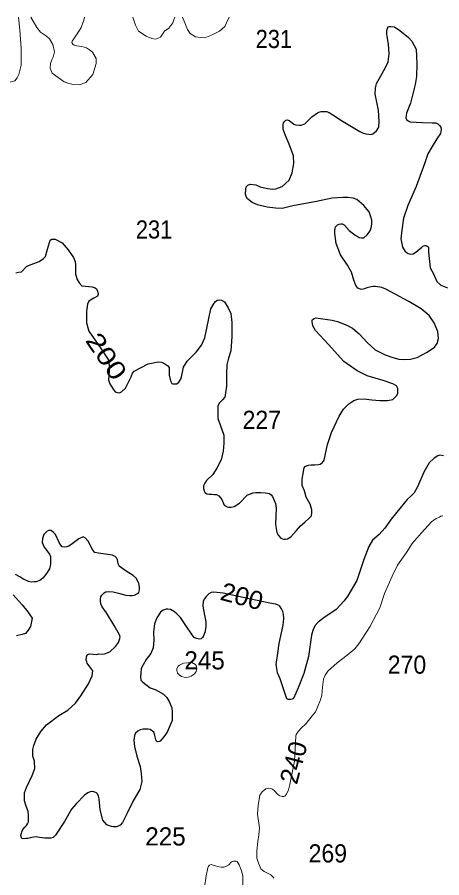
# Model space of a CAD drawing. Extents: x 445.4 to 500, y 8728.7 to 8784.
# Drawn here: x 489.69 to 493.44, y 8776.42 to 8784.01 of the extents above; entities that cross this region are included whole.
import ezdxf
from ezdxf.enums import TextEntityAlignment as Align

# ---------------------------------------------------------------- set-up
doc = ezdxf.new("R2010")
doc.units = 0
doc.header["$LTSCALE"] = 0.064
doc.layers.add('1', color=7, linetype='Continuous', lineweight=25)
doc.layers.add('2', color=7, linetype='Continuous', lineweight=13)
doc.layers.add('21', color=7, linetype='Continuous')
doc.layers.add('61', color=7, linetype='Continuous')

msp = doc.modelspace()

# ---------------------------------------------------------------- linework, layer by layer
at = {"layer": '1'}
for points in [[(492.1344, 8782.7141), (492.1312, 8782.7843), (492.095, 8782.8864), (492.0663, 8782.9468), (492.0418, 8783.0159), (492.0407, 8783.0414), (492.0418, 8783.0606), (492.0439, 8783.0744), (492.0524, 8783.0872), (492.0642, 8783.0967), (492.0759, 8783.0999), (492.094, 8783.0936), (492.1174, 8783.0765), (492.1344, 8783.0627), (492.1525, 8783.0553), (492.1813, 8783.0531), (492.2004, 8783.0531), (492.2313, 8783.0659), (492.2952, 8783.1276), (492.3431, 8783.1627), (492.3559, 8783.1691), (492.3771, 8783.1733), (492.407, 8783.1733), (492.4229, 8783.1733), (492.4463, 8783.1648), (492.4794, 8783.1446), (492.5549, 8783.0936), (492.6281, 8783.0495), (492.7165, 8782.9985), (492.741, 8782.9868), (492.7708, 8782.9783), (492.7963, 8782.973), (492.8155, 8782.9709), (492.8336, 8782.9772), (492.8655, 8783.0049), (492.8847, 8783.0357), (492.889, 8783.0846), (492.8808, 8783.1864), (492.852, 8783.3257), (492.8553, 8783.3806), (492.8638, 8783.4199), (492.899, 8783.4826), (492.9426, 8783.5624), (492.9684, 8783.6132), (492.9769, 8783.6833), (492.9716, 8783.7684), (492.9577, 8783.8354), (492.9556, 8783.8599), (492.9566, 8783.8833), (492.963, 8783.9077), (492.9705, 8783.9194), (492.9769, 8783.9237), (492.9918, 8783.9247), (493.0237, 8783.9194), (493.0706, 8783.8875), (493.1472, 8783.828), (493.177, 8783.7939), (493.2143, 8783.7248), (493.2217, 8783.593), (493.2176, 8783.4815), (493.2059, 8783.4114), (493.1654, 8783.2487), (493.1291, 8783.1595), (493.1259, 8783.1404), (493.1237, 8783.118), (493.1291, 8783.1042), (493.145, 8783.0904), (493.1631, 8783.083), (493.2685, 8783.0776), (493.3548, 8783.0755), (493.3878, 8783.0734), (493.4048, 8783.0659), (493.4208, 8783.0511), (493.4325, 8783.0351), (493.4367, 8783.016), (493.4293, 8782.9798), (493.3973, 8782.932), (493.3554, 8782.8664), (493.3182, 8782.8013), (493.2902, 8782.7199), (493.2157, 8782.5133), (493.1412, 8782.3459), (493.1038, 8782.2328), (493.0871, 8782.1267), (493.0796, 8782.0523), (493.0945, 8781.9778), (493.1187, 8781.9406), (493.1448, 8781.922), (493.1672, 8781.9146), (493.1877, 8781.9174), (493.2125, 8781.9327), (493.2638, 8781.9789), (493.2749, 8781.9849), (493.2903, 8781.9908), (493.3014, 8781.9925), (493.31, 8781.99), (493.3228, 8781.9789), (493.3237, 8781.9327), (493.3391, 8781.7944), (493.3666, 8781.7425), (493.3982, 8781.6733)], [(492.5767, 8780.9688), (492.4404, 8781.1198), (492.3251, 8781.2429), (492.3038, 8781.2823), (492.2985, 8781.3004), (492.2974, 8781.3184), (492.2963, 8781.3323), (492.2995, 8781.3408), (492.3134, 8781.3482), (492.3283, 8781.3535), (492.3485, 8781.3525), (492.4731, 8781.3323), (492.5199, 8781.3227), (492.6029, 8781.2908), (492.6519, 8781.2642), (492.7113, 8781.2116), (492.7815, 8781.1361), (492.8539, 8781.0734), (492.9423, 8781.0266), (493.0083, 8781.0053), (493.0605, 8780.9894), (493.1158, 8780.9873), (493.1644, 8780.9901), (493.225, 8781.005), (493.3123, 8781.0517), (493.3752, 8781.0943), (493.4011, 8781.128), (493.4106, 8781.1705), (493.4053, 8781.2333), (493.3723, 8781.3098), (493.3297, 8781.3736), (493.2584, 8781.4332), (493.1514, 8781.4969), (492.9459, 8781.6075), (492.9123, 8781.6203), (492.8569, 8781.6309), (492.8356, 8781.6309), (492.8175, 8781.6288), (492.7781, 8781.6181), (492.7579, 8781.6086), (492.7355, 8781.6054), (492.7228, 8781.6064), (492.6993, 8781.6149), (492.6823, 8781.6394), (492.6642, 8781.6862), (492.6429, 8781.7564), (492.6085, 8781.8198), (492.5478, 8781.9102), (492.5095, 8782.0102), (492.4978, 8782.098), (492.4967, 8782.1257), (492.4989, 8782.1459), (492.5031, 8782.1555), (492.5116, 8782.1661), (492.5212, 8782.1735), (492.535, 8782.181), (492.5489, 8782.1831), (492.5606, 8782.1831), (492.5798, 8782.1746), (492.6234, 8782.1236), (492.6756, 8782.0832), (492.6947, 8782.0736), (492.7128, 8782.064), (492.7331, 8782.0598), (492.7533, 8782.0598), (492.781, 8782.0874), (492.8076, 8782.1204), (492.8172, 8782.148), (492.8236, 8782.1789), (492.8225, 8782.2161), (492.814, 8782.2448), (492.8012, 8782.2895), (492.7533, 8782.3448), (492.6914, 8782.3965), (492.6574, 8782.4082), (492.6159, 8782.4146), (492.568, 8782.4146), (492.4732, 8782.4093), (492.3337, 8782.3795), (492.1261, 8782.3412), (492.0316, 8782.3196), (491.972, 8782.3207), (491.8985, 8782.3313), (491.8155, 8782.3505), (491.7665, 8782.3707), (491.7271, 8782.4047), (491.7133, 8782.4249), (491.708, 8782.4462), (491.7101, 8782.4898), (491.7144, 8782.5089), (491.7293, 8782.5249), (491.7506, 8782.5323), (491.7985, 8782.5259), (491.8389, 8782.51), (491.9017, 8782.494), (491.9481, 8782.4903), (491.9768, 8782.4924), (492.0311, 8782.5126), (492.095, 8782.569), (492.1216, 8782.6328), (492.1344, 8782.7141)], [(489.6822, 8781.7506), (489.7035, 8781.7556), (489.7298, 8781.7605), (489.7758, 8781.8064), (489.7922, 8781.8146), (489.8857, 8781.8506), (489.9251, 8781.8769), (489.9431, 8781.8949), (489.9612, 8781.9588), (489.977, 8782.018), (489.9852, 8782.0393), (490, 8782.0492), (490.0279, 8782.0492), (490.0886, 8782.0148), (490.1428, 8781.9541), (490.1904, 8781.8869), (490.2051, 8781.8508), (490.2084, 8781.8197), (490.2084, 8781.7394), (490.2232, 8781.6935), (490.2398, 8781.6629), (490.2645, 8781.6367), (490.2956, 8781.6334), (490.3547, 8781.6268), (490.381, 8781.6186), (490.3925, 8781.6088), (490.4007, 8781.5891), (490.4072, 8781.5629), (490.4007, 8781.5449), (490.3695, 8781.5285), (490.3252, 8781.5023), (490.312, 8781.4744), (490.3055, 8781.4121), (490.3055, 8781.3105), (490.3252, 8781.2372), (490.4352, 8781.0799), (490.4959, 8780.9881), (490.509, 8780.9192), (490.4992, 8780.8061), (490.5095, 8780.7723), (490.539, 8780.7264), (490.5571, 8780.7018), (490.5751, 8780.6952), (490.5964, 8780.6936), (490.6129, 8780.7002), (490.649, 8780.733), (490.6982, 8780.8346), (490.7113, 8780.8657), (490.7261, 8780.8838), (490.8492, 8780.9477), (490.9361, 8780.9657), (490.9673, 8780.9624), (490.9883, 8780.9537), (491.0213, 8780.9303), (491.0341, 8780.9175), (491.0352, 8780.8473), (491.0448, 8780.7984), (491.0565, 8780.7761), (491.066, 8780.7718), (491.082, 8780.7708), (491.1022, 8780.7729), (491.1203, 8780.7857), (491.1406, 8780.8197), (491.1597, 8780.9197), (491.1938, 8780.9728), (491.2736, 8781.0526), (491.3188, 8781.1118), (491.3497, 8781.1778), (491.3859, 8781.3469), (491.4031, 8781.4338), (491.4307, 8781.4837), (491.4414, 8781.4965), (491.4595, 8781.5093), (491.4755, 8781.5125), (491.4978, 8781.5114), (491.5223, 8781.4954), (491.5564, 8781.4412), (491.5787, 8781.3934), (491.5872, 8781.3125), (491.5885, 8781.1884), (491.5789, 8781.064), (491.5576, 8780.9973), (491.5448, 8780.9388), (491.5405, 8780.8602)], [(493.3982, 8781.6733), (493.4333, 8781.6417), (493.4905, 8781.6195)], [(491.5405, 8780.8602), (491.5405, 8780.7506), (491.5309, 8780.6924), (491.5245, 8780.6552), (491.5065, 8780.6318), (491.4745, 8780.602), (491.4649, 8780.5744), (491.4628, 8780.5138), (491.4649, 8780.4659), (491.4852, 8780.4111), (491.516, 8780.3185), (491.516, 8780.2473), (491.5097, 8780.1771), (491.4926, 8780.1018), (491.4564, 8780.0273), (491.4202, 8779.972), (491.3627, 8779.9199), (491.3478, 8779.8965), (491.3382, 8779.871), (491.3382, 8779.8498), (491.3425, 8779.8296), (491.3478, 8779.8147), (491.3672, 8779.8013), (491.3863, 8779.8002), (491.4097, 8779.7992), (491.4353, 8779.7971), (491.4534, 8779.7949), (491.4715, 8779.7854), (491.4981, 8779.7524), (491.5194, 8779.7013), (491.545, 8779.6875), (491.5599, 8779.6854), (491.5822, 8779.6843), (491.6088, 8779.6897), (491.6557, 8779.7194), (491.7227, 8779.7896), (491.7717, 8779.8109), (491.7994, 8779.8141), (491.8409, 8779.8151), (491.8835, 8779.8109), (491.9186, 8779.8056), (491.9346, 8779.7928), (491.9474, 8779.779), (491.9719, 8779.7173), (491.9787, 8779.6753), (491.9734, 8779.5328), (491.9851, 8779.4615), (491.9989, 8779.435), (492.0202, 8779.4094), (492.0351, 8779.4041), (492.0479, 8779.4031), (492.0607, 8779.4031), (492.0777, 8779.4062), (492.1086, 8779.4222), (492.1576, 8779.4786), (492.1938, 8779.5211), (492.231, 8779.5509), (492.2715, 8779.586), (492.2896, 8779.6083), (492.2949, 8779.6338), (492.2938, 8779.6615), (492.2779, 8779.7114), (492.245, 8779.7717), (492.2291, 8779.8292), (492.2078, 8779.8759), (492.2078, 8779.9302), (492.2269, 8780.0312), (492.2345, 8780.0426), (492.2462, 8780.0501), (492.2654, 8780.0543), (492.2867, 8780.0575), (492.3197, 8780.0575), (492.3516, 8780.0618), (492.3665, 8780.065), (492.3804, 8780.0713), (492.3889, 8780.0788), (492.4038, 8780.0979), (492.4315, 8780.2372), (492.4666, 8780.3425), (492.5341, 8780.4879), (492.5735, 8780.5485), (492.6203, 8780.5942), (492.664, 8780.625), (492.6991, 8780.6357), (492.7555, 8780.6389), (492.8231, 8780.63), (492.8944, 8780.6247), (492.9626, 8780.6236), (493.0094, 8780.6353), (493.0264, 8780.6513), (493.0445, 8780.6683), (493.0531, 8780.6885), (493.0531, 8780.7066), (493.0531, 8780.7299), (493.0477, 8780.7438), (493.0403, 8780.7555), (493.0083, 8780.7725), (492.9242, 8780.8012), (492.7816, 8780.8416), (492.6938, 8780.888), (492.5767, 8780.9688)], [(493.4559, 8780.1383), (493.4248, 8780.142), (493.4047, 8780.1365), (493.3736, 8780.1173), (493.3306, 8780.0753), (493.2828, 8779.9916), (493.2279, 8779.8628), (493.197, 8779.8113), (493.1673, 8779.7799), (493.1341, 8779.752), (493.0428, 8779.6413), (492.9939, 8779.5784), (492.938, 8779.4982), (492.8891, 8779.4424), (492.828, 8779.3918), (492.7983, 8779.3359), (492.7542, 8779.2214), (492.6896, 8779.0365), (492.6101, 8778.903), (492.5791, 8778.8567), (492.5075, 8778.7812), (492.3986, 8778.7073), (492.3483, 8778.6689), (492.32, 8778.6366), (492.3026, 8778.5963), (492.2918, 8778.5547), (492.2649, 8778.368), (492.2245, 8778.2181), (492.1734, 8778.0918), (492.1317, 8777.9978), (492.121, 8777.991), (492.1089, 8777.9884), (492.0994, 8777.9884), (492.086, 8777.9884), (492.0739, 8777.9951), (492.0698, 8778.0031), (492.0134, 8778.171), (491.9905, 8778.2221), (491.9878, 8778.2422), (491.9851, 8778.2637), (491.9797, 8778.2973), (491.9945, 8778.3954), (492.0068, 8778.4823), (492.0417, 8778.6435), (492.0458, 8778.7013), (492.0431, 8778.7403), (492.0377, 8778.7631), (492.0269, 8778.7873), (492.0108, 8778.8115), (491.992, 8778.8222), (491.9718, 8778.8276), (491.9217, 8778.8365), (491.7563, 8778.8714), (491.512, 8778.9252), (491.4299, 8778.936), (491.4057, 8778.9319), (491.3842, 8778.9185), (491.36, 8778.897), (491.3465, 8778.8769), (491.3358, 8778.8554), (491.3304, 8778.811), (491.3452, 8778.7304), (491.3573, 8778.6717), (491.3573, 8778.6287), (491.3506, 8778.579), (491.3385, 8778.5481), (491.3277, 8778.5333), (491.3156, 8778.5226), (491.3008, 8778.5199), (491.2766, 8778.5266), (491.2565, 8778.5333), (491.2363, 8778.5575), (491.1811, 8778.6408), (491.1341, 8778.712), (491.1031, 8778.7442), (491.0803, 8778.7617), (491.0474, 8778.782), (491.0219, 8778.7847), (491.0084, 8778.7847), (490.9802, 8778.7753), (490.9587, 8778.7579), (490.9264, 8778.7095), (490.9049, 8778.6558), (490.8968, 8778.5859), (490.8981, 8778.5093), (490.8926, 8778.444), (490.8725, 8778.3929), (490.8321, 8778.3406)], [(489.849, 8777.378), (489.8449, 8777.4438), (489.8315, 8777.4895), (489.8301, 8777.5137), (489.8301, 8777.5459), (489.8395, 8777.5835), (489.8611, 8777.6373), (489.9001, 8777.7071), (489.9515, 8777.7657), (490.0604, 8777.8463), (490.1411, 8777.8947), (490.207, 8777.9565), (490.2544, 8778.0191), (490.323, 8778.1266), (490.3533, 8778.1963), (490.36, 8778.2396), (490.3333, 8778.2762), (490.3099, 8778.3095), (490.3066, 8778.3212), (490.3016, 8778.3379), (490.3049, 8778.3628), (490.3133, 8778.3845), (490.33, 8778.3895), (490.3633, 8778.3878), (490.3917, 8778.3862), (490.4117, 8778.3895), (490.445, 8778.3878), (490.4634, 8778.3912), (490.5117, 8778.4095), (490.562, 8778.4553), (490.587, 8778.4903), (490.597, 8778.517), (490.6004, 8778.5386), (490.597, 8778.5586), (490.5503, 8778.6419), (490.482, 8778.7535), (490.442, 8778.8064), (490.432, 8778.8313), (490.4286, 8778.858), (490.427, 8778.878), (490.4303, 8778.893), (490.4386, 8778.908), (490.4503, 8778.9196), (490.462, 8778.9296), (490.4753, 8778.9363), (490.5003, 8778.9396), (490.5404, 8778.9379), (490.5871, 8778.9246), (490.6521, 8778.908), (490.6838, 8778.9063), (490.7071, 8778.9063), (490.7271, 8778.908), (490.7538, 8778.923), (490.7655, 8778.933), (490.7722, 8778.9563), (490.7722, 8778.9796), (490.7672, 8779.0112), (490.7455, 8779.0562), (490.7155, 8779.0829), (490.6538, 8779.1212), (490.6137, 8779.1495), (490.5937, 8779.1645), (490.5937, 8779.1645), (490.5837, 8779.1861), (490.5821, 8779.2061), (490.5771, 8779.2195), (490.5687, 8779.2361), (490.557, 8779.2494), (490.5333, 8779.2623), (490.4716, 8779.269), (490.4116, 8779.279), (490.3782, 8779.2856), (490.3599, 8779.3039), (490.3182, 8779.3856), (490.2965, 8779.4122), (490.2765, 8779.4222), (490.2365, 8779.4056), (490.1781, 8779.3622), (490.1481, 8779.3389), (490.1297, 8779.3339), (490.1081, 8779.3323), (490.0897, 8779.3356), (490.078, 8779.3489), (490.0647, 8779.3722), (490.0297, 8779.4422), (490.0147, 8779.4622), (489.9913, 8779.4788), (489.973, 8779.4788), (489.9563, 8779.4738), (489.928, 8779.4439), (489.9163, 8779.4072), (489.9146, 8779.3722), (489.9296, 8779.3306), (489.978, 8779.2706), (489.988, 8779.2506), (489.9855, 8779.1814), (489.9789, 8779.1398), (489.9522, 8779.0981), (489.9188, 8779.0581), (489.8922, 8779.0365), (489.8605, 8779.0248)], [(489.8605, 8779.0248), (489.8421, 8779.0248), (489.8188, 8779.0232), (489.7921, 8779.0282), (489.7437, 8779.0515), (489.7154, 8779.0698), (489.6787, 8779.0898)], [(489.6587, 8778.9116), (489.7354, 8778.8233), (489.7855, 8778.7605), (489.8055, 8778.7339), (489.8238, 8778.7039), (489.8105, 8778.6306), (489.7888, 8778.6006), (489.7671, 8778.569), (489.7354, 8778.5606), (489.6854, 8778.5506)], [(490.8321, 8778.3406), (490.8039, 8778.2949), (490.7877, 8778.26), (490.785, 8778.221), (490.7823, 8778.1888), (490.785, 8778.1592), (490.8012, 8778.1404), (490.8657, 8778.092), (490.9104, 8778.0749), (490.9844, 8778.0346), (491.0127, 8778.0064), (491.0355, 8777.9701), (491.0584, 8777.915), (491.0611, 8777.876), (491.0597, 8777.8022), (491.018, 8777.6987), (490.9881, 8777.6575), (490.9558, 8777.6212), (490.949, 8777.6185), (490.949, 8777.6185), (490.9289, 8777.6145), (490.9222, 8777.6212), (490.9181, 8777.6319), (490.9141, 8777.6481), (490.9087, 8777.6696), (490.8979, 8777.6991), (490.867, 8777.7246), (490.8468, 8777.7273), (490.8038, 8777.726), (490.7769, 8777.7193), (490.7567, 8777.7099), (490.7379, 8777.691), (490.7271, 8777.6709), (490.7218, 8777.6279), (490.7298, 8777.5728), (490.7487, 8777.4869), (490.7769, 8777.3982), (490.7877, 8777.3355), (490.7944, 8777.2657), (490.7742, 8777.1945), (490.7177, 8777.095), (490.664, 8776.9862), (490.6219, 8776.902), (490.6031, 8776.8805), (490.5909, 8776.8725), (490.5775, 8776.8671), (490.5694, 8776.8658), (490.5439, 8776.8644), (490.525, 8776.8684), (490.5076, 8776.8738), (490.4834, 8776.8832), (490.4659, 8776.9034), (490.4484, 8776.9235), (490.4255, 8777.0135), (490.4173, 8777.111), (490.4092, 8777.1352), (490.4012, 8777.1554), (490.3931, 8777.1634), (490.3796, 8777.1715), (490.3595, 8777.1755), (490.3379, 8777.1742), (490.3164, 8777.1634), (490.2882, 8777.1446), (490.2129, 8777.0681), (490.1733, 8777.0204), (490.1115, 8776.9129), (490.0321, 8776.792), (490.0106, 8776.7705), (489.9891, 8776.7638), (489.9824, 8776.7638), (489.9649, 8776.7638), (489.938, 8776.7638), (489.9151, 8776.7678), (489.8909, 8776.7705), (489.86, 8776.7772), (489.8385, 8776.7746), (489.821, 8776.7705), (489.786, 8776.7625), (489.7699, 8776.7611), (489.7511, 8776.7598), (489.7349, 8776.7611), (489.7295, 8776.7678), (489.7295, 8776.7678), (489.7255, 8776.7893), (489.7295, 8776.8081), (489.7349, 8776.8216), (489.743, 8776.8417), (489.7605, 8776.8619), (489.7739, 8776.878), (489.7833, 8776.8901), (489.7914, 8776.9102), (489.7927, 8776.9358), (489.7927, 8776.9667), (489.7901, 8776.9989), (489.7685, 8777.0567), (489.7575, 8777.0936), (489.7575, 8777.1232), (489.7575, 8777.1662), (489.775, 8777.2118), (489.8247, 8777.3166), (489.849, 8777.378)]]:
    msp.add_lwpolyline(points, dxfattribs=at)
at = {"layer": '2'}
for points in [[(489.2057, 8784.0049), (489.2054, 8783.9521), (489.2246, 8783.9234), (489.2318, 8783.8971), (489.2342, 8783.8445), (489.2509, 8783.7609), (489.337, 8783.6486), (489.5213, 8783.467), (489.5452, 8783.4455), (489.5787, 8783.4408), (489.6122, 8783.4288), (489.6481, 8783.4384), (489.672, 8783.4455), (489.6935, 8783.4718), (489.7079, 8783.5005), (489.727, 8783.5817), (489.727, 8783.7322), (489.7175, 8783.8899), (489.7029, 8784.005)], [(489.814, 8784.0051), (489.8658, 8783.9138), (489.8993, 8783.8732), (489.9519, 8783.8374), (489.9783, 8783.8135), (490.007, 8783.7657), (490.0213, 8783.7012), (490.0117, 8783.6534), (489.9998, 8783.6295), (489.9878, 8783.5961), (489.983, 8783.5554), (490.0022, 8783.5124), (490.1075, 8783.436), (490.1481, 8783.4216), (490.1888, 8783.4121), (490.239, 8783.4097), (490.2989, 8783.4312), (490.3611, 8783.5005), (490.3898, 8783.5961), (490.3898, 8783.6415), (490.3587, 8783.6964), (490.33, 8783.7179), (490.3036, 8783.7346), (490.263, 8783.7466), (490.2438, 8783.749), (490.2175, 8783.7538), (490.196, 8783.7585), (490.184, 8783.7681), (490.1744, 8783.7824), (490.1768, 8783.7944), (490.1936, 8783.8135), (490.2343, 8783.8756), (490.2582, 8783.9138), (490.2821, 8783.9807), (490.2864, 8784.0052)], [(490.7139, 8784.0054), (490.7363, 8783.9366), (490.7649, 8783.8835), (490.8303, 8783.8385), (490.8815, 8783.8181), (490.9142, 8783.812), (490.9592, 8783.8304), (490.9939, 8783.8814), (491.0307, 8783.91), (491.0655, 8783.957), (491.0757, 8783.9815), (491.0845, 8784.0055)], [(491.1534, 8784.0055), (491.1718, 8783.955), (491.1963, 8783.8978), (491.2209, 8783.861), (491.2679, 8783.8324), (491.3067, 8783.8263), (491.364, 8783.8304), (491.4069, 8783.8467), (491.4785, 8783.8814), (491.5255, 8783.9243), (491.5419, 8783.957), (491.5637, 8784.0056)], [(492.1551, 8777.6793), (492.1764, 8777.7073), (492.1989, 8777.7365), (492.2427, 8777.7758), (492.2978, 8777.8431), (492.3249, 8777.8799), (492.3451, 8777.9192), (492.3698, 8777.9843), (492.3822, 8778.027), (492.3878, 8778.0965), (492.3958, 8778.1682), (492.4116, 8778.203), (492.4352, 8778.2378), (492.5172, 8778.3119), (492.606, 8778.3781), (492.6723, 8778.4342), (492.7075, 8778.4797), (492.8053, 8778.629), (492.8952, 8778.7963), (492.9358, 8778.9239), (493.0032, 8779.0754), (493.0495, 8779.1716), (493.1281, 8779.2849), (493.1787, 8779.3635), (493.2623, 8779.4575), (493.3488, 8779.554), (493.3926, 8779.5843), (493.4196, 8779.5966), (493.4319, 8779.6045), (493.4488, 8779.609)], [(491.9585, 8776.4118), (491.951, 8776.4211), (491.9304, 8776.4417), (491.8733, 8776.4698), (491.8443, 8776.4959), (491.8321, 8776.5249), (491.8237, 8776.5455), (491.8077, 8776.5873), (491.8086, 8776.6518), (491.818, 8776.7351), (491.8264, 8776.7931), (491.8321, 8776.8563), (491.8133, 8776.976), (491.819, 8777.0534), (491.8339, 8777.1432), (491.8555, 8777.175), (491.8864, 8777.2012), (491.9098, 8777.2049), (491.9285, 8777.204), (491.9472, 8777.1974), (491.9669, 8777.1787), (491.9894, 8777.1544), (492.0053, 8777.1422), (492.0119, 8777.1376), (492.0222, 8777.1348), (492.0315, 8777.1338), (492.0428, 8777.1329), (492.0549, 8777.1357), (492.0709, 8777.1525), (492.0868, 8777.1909), (492.0989, 8777.2377), (492.1416, 8777.4432), (492.1517, 8777.6647), (492.1551, 8777.6793)], [(491.3473, 8776.3332), (491.3605, 8776.4314), (491.3745, 8776.5044), (491.3829, 8776.5184), (491.3914, 8776.5259), (491.4045, 8776.5315), (491.4129, 8776.5306), (491.4316, 8776.524), (491.4747, 8776.5128), (491.4962, 8776.5081), (491.5159, 8776.51), (491.5356, 8776.5147), (491.5609, 8776.5297), (491.5824, 8776.5521), (491.5918, 8776.5577), (491.6011, 8776.5615), (491.6124, 8776.5624), (491.6255, 8776.5624), (491.6339, 8776.5587), (491.6517, 8776.5287), (491.6732, 8776.4773), (491.6845, 8776.4314), (491.6845, 8776.3435)]]:
    msp.add_lwpolyline(points, dxfattribs=at)
msp.add_lwpolyline([(491.2334, 8778.3133), (491.1611, 8778.3083), (491.1258, 8778.2915), (491.1141, 8778.2831), (491.1023, 8778.2613), (491.1023, 8778.2428), (491.109, 8778.221), (491.1225, 8778.2042), (491.1426, 8778.1907), (491.1662, 8778.184), (491.1914, 8778.1823), (491.2133, 8778.1874), (491.2284, 8778.1941), (491.2469, 8778.2042), (491.262, 8778.2176), (491.2738, 8778.2361), (491.2789, 8778.2613), (491.2721, 8778.2864), (491.2587, 8778.3016), (491.2486, 8778.3066)], close=True, dxfattribs=at)

# ---------------------------------------------------------------- texts
at = {"layer": '21', "width": 0.9}
msp.add_text('231', height=0.16, dxfattribs=at).set_placement((492.1193, 8783.7337), align=Align.RIGHT)
at = {"layer": '21'}
for s, width, p in [('231', 0.9, (490.7404, 8782.0535)), ('227', 0.95, (491.6827, 8780.3748)), ('270', 0.95, (492.9642, 8778.2154)), ('269', 0.95, (492.2653, 8776.5509))]:
    msp.add_text(s, height=0.16, dxfattribs=dict(at, width=width)).set_placement(p)
for s, p in [('245', (491.1684, 8778.2533)), ('225', (490.8234, 8776.7003))]:
    msp.add_text(s, height=0.16, dxfattribs=at).set_placement(p)
at = {"layer": '61'}
for s, rotation, width, p in [('200', 304.368, 1.25, (490.4142, 8780.9702)), ('200', 345.011, 1.05, (491.6564, 8778.8211)), ('240', 75.081, 1.05, (492.2096, 8777.4114))]:
    msp.add_text(s, height=0.16, rotation=rotation, dxfattribs=dict(at, width=width)).set_placement(p, align=Align.CENTER)

doc.saveas('drawing.dxf')
